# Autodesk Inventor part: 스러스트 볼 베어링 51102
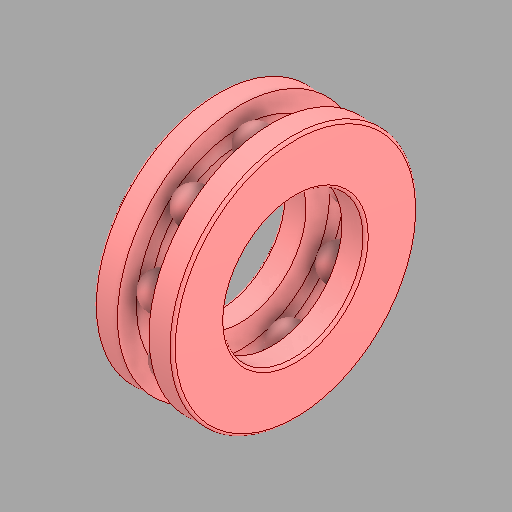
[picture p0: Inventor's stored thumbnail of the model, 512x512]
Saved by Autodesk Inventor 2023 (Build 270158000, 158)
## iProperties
Created: 2025-09
Part Number: 스러스트 볼 베어링 51102
Material: 강철, 연강
Description: 롤링 베어링 - 플랫 뒷면이 있는 스러스트 볼 베어링
Document SubType Name: Modeling
Designer: home
Density: 7.85 g/cm^3
Appearance: 기본값
Author: jhkim
Sending System: Autodesk Inventor 2026
Preprocessor: ST-DEVELOPER v20.1
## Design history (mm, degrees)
feature "Solid1"
feature "Solid1:1"
feature "Solid1:2"
feature "Solid1:3"
feature "Solid1:4"
feature "Solid1:5"
feature "Solid1:6"
feature "Solid1:7"
feature "Solid1:8"
feature "Solid1:9"
feature "Solid1:10"
node "솔리드1"
node "솔리드2"
node "솔리드3"
node "솔리드4"
node "솔리드5"
node "솔리드6"
node "솔리드7"
node "솔리드8"
node "솔리드9"
node "솔리드10"
node "솔리드11"
